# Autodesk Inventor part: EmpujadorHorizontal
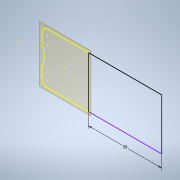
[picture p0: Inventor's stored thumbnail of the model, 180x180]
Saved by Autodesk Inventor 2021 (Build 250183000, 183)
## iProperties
Created: 2021-02
Part Number: EmpujadorHorizontal
Material: Genérico
Document SubType Name: Modeling
Designer: ATOUZA
Density: 1 g/cm^3
Appearance: Valor por defecto
Author: ATOUZA
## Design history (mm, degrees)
node "Plano de trabajo1"
sketch "Boceto1"
  geometry: L1 (-16, 12)-(-16, 4.71) reference; L2 (-16, -7.71)-(-16, -12) reference; L3 (-12, -16)-(16, -16) reference; L4 (16, -16)-(16, 16) reference; L5 (16, 16)-(-12, 16) reference; L6 (16, 16)-(66, 16); L7 (66, 16)-(66, -19); L8 (66, -19)-(16, -19); L9 (16, -19)-(16, 16); A1 r 4 centre (-12, 12) between (-12, 16) and (-16, 12) reference; A2 r 4 centre (-12, 4.71) between (-16, 4.71) and (-15.83, 3.555) reference; A3 r 17.5 centre (-32.584, -1.5) between (-15.83, -6.555) and (-15.83, 3.555) reference; A4 r 4 centre (-12, -7.71) between (-15.83, -6.555) and (-16, -7.71) reference; A5 r 4 centre (-12, -12) between (-16, -12) and (-12, -16) reference; 1 further point
  constraints: 8 end point, 2 parallel, 1 horizontal, 1 perpendicular
  dimensions: "d0" = 50 distance of L7.end L8.end
  node "Referencia1"
